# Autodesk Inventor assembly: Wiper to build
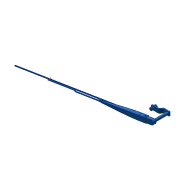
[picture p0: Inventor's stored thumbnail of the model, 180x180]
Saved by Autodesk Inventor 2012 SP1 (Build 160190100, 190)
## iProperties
Created: 2006-03
Part Number: Wiper to build
Document SubType Name: Assembly
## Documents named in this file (5)
- D:\Backup\Autodesk Motion Files\Inv2012DynSim\Sub-Assemblies\Complete_wiper_left_asm.iam
- D:\Backup\Autodesk Motion Files\Inv2012DynSim\Parts\Axis_Left.ipt
- D:\Backup\Autodesk Motion Files\Inv2012DynSim\Parts\Support_Wiper.ipt
- D:\Backup\Autodesk Motion Files\Inv2012DynSim\Parts\Crank_left.ipt
- D:\Backup\Autodesk Motion Files\Inv2012DynSim\Parts\Pawn_3.ipt
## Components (4 placed, 4 different names)
1. Crank_left:1 — Mate:31, Mate:32, Mate:33, Mate:34, Mate:35, Mate:36, Mate:37, Mate:38
2. Axis_Left:1 — Mate:17, Flush:3, Angle:8, Mate:34, Mate:35, Mate:36
3. Support_Wiper:2 — Mate:17, Flush:3, Angle:8
4. Pawn_3:1 — Mate:37, Mate:38
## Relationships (11: Mate 9, Flush 1, Angle 1)
- Mate:17: Axis_Left:1 ↔ Support_Wiper:2
- Flush:3: Axis_Left:1 ↔ Support_Wiper:2
- Angle:8: Axis_Left:1 ↔ Support_Wiper:2
- Mate:31: Crank_left:1
- Mate:32: Crank_left:1
- Mate:33: Crank_left:1
- Mate:34: Crank_left:1 ↔ Axis_Left:1
- Mate:35: Crank_left:1 ↔ Axis_Left:1
- Mate:36: Crank_left:1 ↔ Axis_Left:1
- Mate:37: Crank_left:1 ↔ Pawn_3:1
- Mate:38: Crank_left:1 ↔ Pawn_3:1
